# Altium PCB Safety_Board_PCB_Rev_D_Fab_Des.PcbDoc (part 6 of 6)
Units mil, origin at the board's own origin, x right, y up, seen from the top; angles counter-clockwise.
Board outline 11000 x 4400 mil, 6 copper layers (L1-TOP, L2-Plane, L3-Signal, L4-Signal, L5-Plane, L6-BOT); 712 components, 540 nets, 2214 pads, 875 vias.
Unrouted connection lines stored in the file: 3.
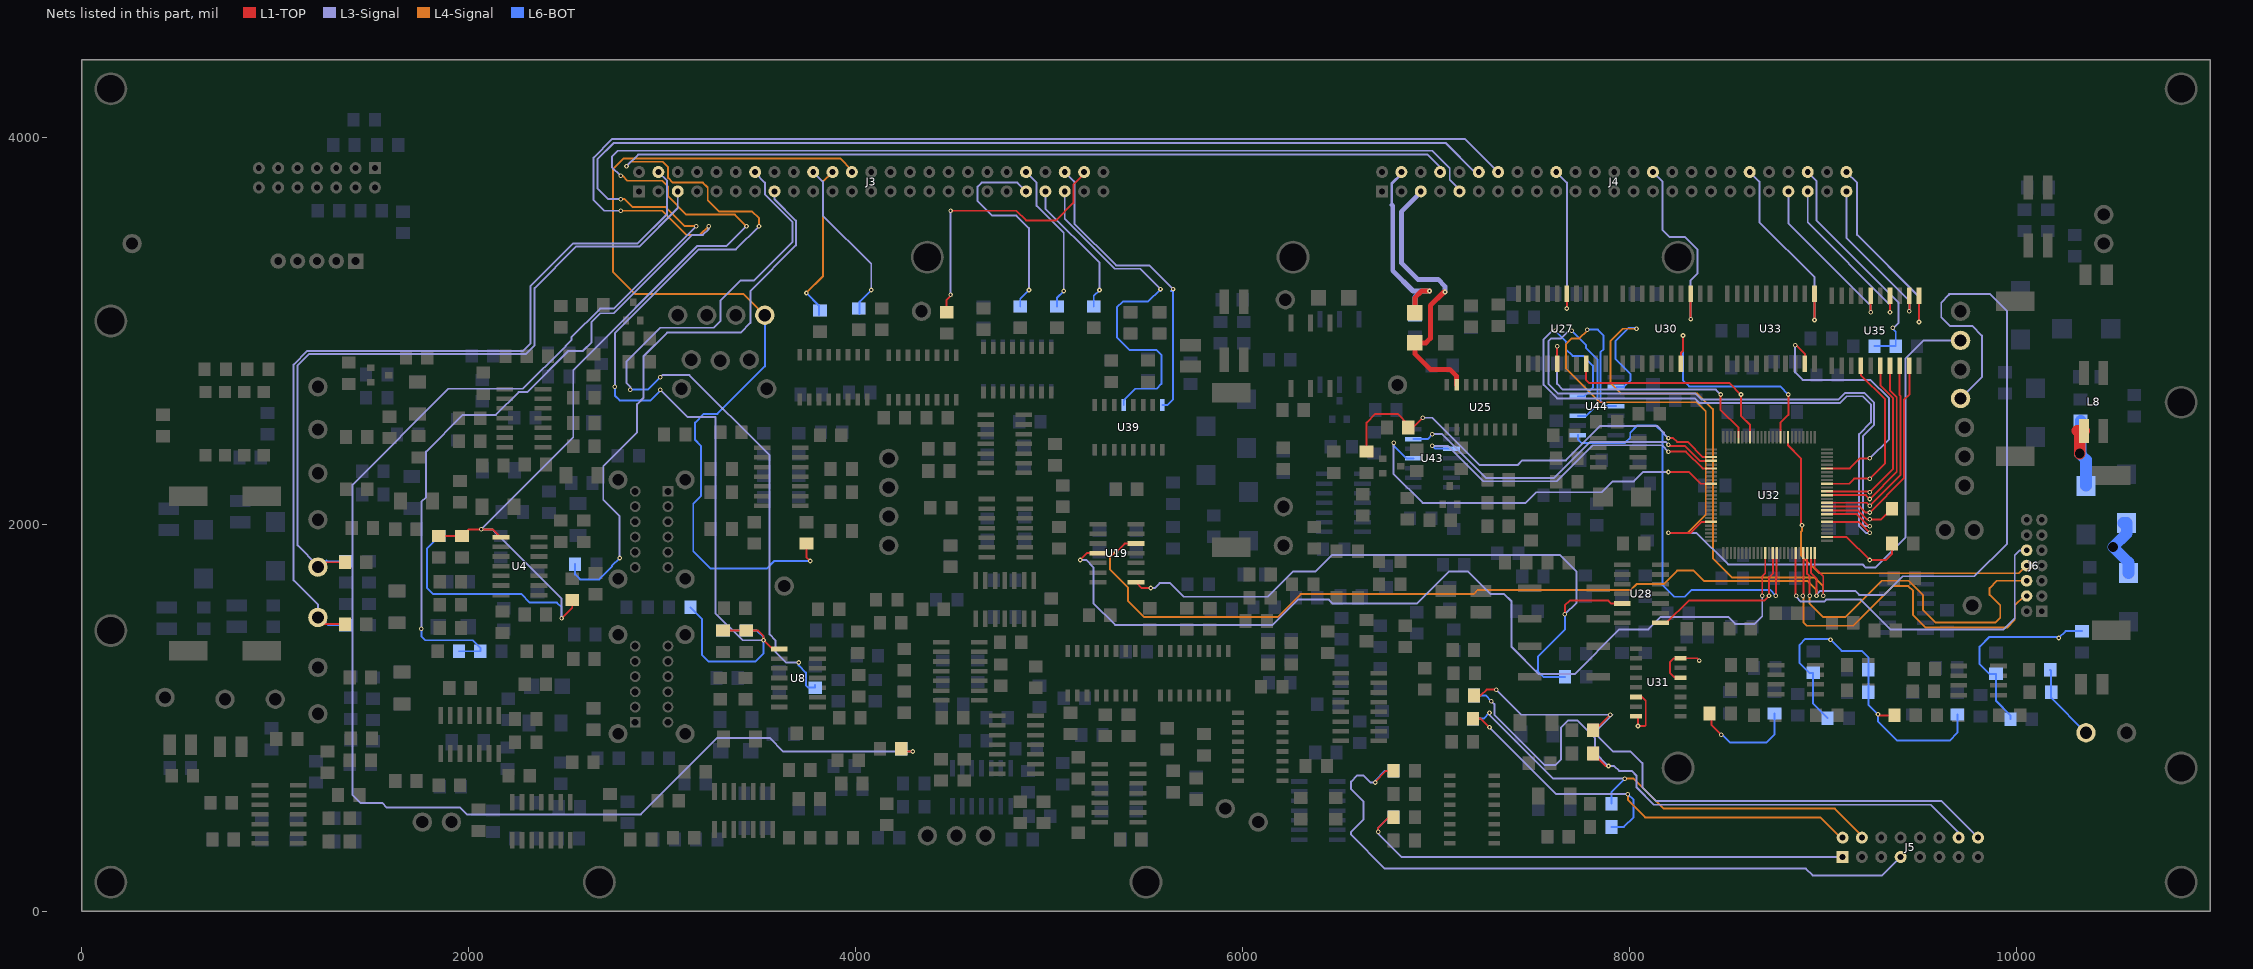
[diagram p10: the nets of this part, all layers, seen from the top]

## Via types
v1: diameter 24, hole 12, L1-TOP to L6-BOT, 720 vias
v2: diameter 50, hole 28, L1-TOP to L6-BOT, 138 vias
v3: diameter 28, hole 50, L1-TOP to L6-BOT, 17 vias

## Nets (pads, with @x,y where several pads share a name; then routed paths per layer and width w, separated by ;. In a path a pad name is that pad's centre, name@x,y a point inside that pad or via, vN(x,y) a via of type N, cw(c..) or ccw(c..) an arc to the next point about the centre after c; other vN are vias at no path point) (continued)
"SOUTH TACH OUT": C9.1 C66.1 J4.9 R26.1 R37.1 R211.1 U4.1 | length 10012.3
  L1-TOP w10: C9.1@1844.65,1938.23 R26.1@1964.65,1938.23 ; R26.1@1969.76,1933.11 R26.1@1964.65,1938.23 ; U4.1@2159.65,1933.11 U4.1@2166.22,1933.11 U4.1@2161.1,1938.23 ; U4.1@2164.65,1933.11 2124.65,1973.11 1999.53,1973.11 R26.1@1964.65,1938.23 ; v1(2479.65,1513.11) 2534.65,1568.11 R37.1@2534.65,1607.99
  L4-Signal w10: v1(2785,3800) 2795,3800 2820,3775 3000,3775 3030,3745 3030,3695 3125,3600 3375,3600 v1(3435,3540)
  L3-Signal w10: v1(2064.65,1973.11) 2121.89,1973.11 2479.65,1615.35 v1(2479.65,1513.11) ; v1@2064.65,1974.65 2540,2450 2540,2795.96 3182.04,3438 3333,3438 v1(3435,3540) ; v1(2785,3800) 2740,3845 2740,3900 2770,3930 6980,3930 7070,3840 7070,3780 7120,3730 J4.9@7120,3720
  L6-BOT w10: C66.1@1968.23,1938.23 R211.1@1844.65,1938.23 1844.65,1934.65 1785,1875 1785,1670 1815,1640 2270,1640 2315,1595 2455,1595 2479.65,1570.35 v1(2479.65,1513.11)
"SOUTH VEL IN": J3.15 R230.2 | length 2953.5
  L3-Signal w10: v1(2780,1825) 2780,2040 2695,2125 2695,2300 2870,2475 2870,2620 2902.98,2652.98 2902.98,2867.98 3025,2990 3405,2990 3455,3040 3455,3205 3691,3441 3691,3569 3580,3680 J3.15@3580,3720
  L6-BOT w10: R230.2@2549.53,1793.11 2549.53,1740.47 2575,1715 2675,1715 2740,1780 2740,1785 v1(2780,1825)
"SOUTH VEL OUT": C67.2 J4.14 R215.2 | length 9152.5
  L4-Signal w10: v1(2785,3620) 3000,3620 3125,3495 3195,3495 v1(3240,3540) 3240,3525
  L3-Signal w10: v1(1755,1460) 1755,2115 1780,2140 1780,2375 1970,2565 2140,2565 2258,2683 2303,2683 2515,2895 2590,2895 2635,2940 2635,3045 2680,3090 2750,3090 3155,3495 3210,3495 3240,3525 v1(3240,3540) ; v1(2785,3620) 2700,3620 2645,3675 2645,3895 2740,3990 7150,3990 J4.14@7320,3820 J4.14@7320,3830
  L6-BOT w10: v1(1755,1460) 1755,1420 1775,1400 2020,1400 2059.53,1360.47 C67.2@2059.53,1343.11 R215.2@1949.76,1343.11
SOUTH_ENCODER_BUF: J5.7 R138.1 R318.2 | length 3695.4
  L1-TOP w10: v1(6685,665) 6685,670 6740,725 R138.1@6779.88,725
  L3-Signal w10: v1(6685,665) 6660,665 6625,700 6590,700 6560,670 6560,630 6625,565 6625,475 6560,410 6560,395 6735,220 8910,220 8945,185 9305,185 J5.7@9400,280
  L6-BOT w10: v1(6685,665) 6685,675 6735,725 R318.2@6779.88,725
SOUTH_ENCODER_IN: J5.14 R166.1 R330.1 | length 3329.8
  L1-TOP w10: R166.1@7810.12,815 7875.12,750 v1(7890,750)
  L3-Signal w10: v1(7285,1085) 7300,1070 7300,1015 7560,755 7615,755 7645,785 7645,950 7680,985 7730.96,985 7820,895.96 7820,820 v1(7890,750) 7920,750 7945,725 8010,725 8035,700 8035,640 8125,550 9555,550 9700,405 J5.14@9700,380
  L6-BOT w10: R330.1@7195.12,1115 7255,1115 v1(7285,1085)
SOUTH_ENCODER_RTN: J5.16 R155.1 R165.1 | length 3330.2
  L1-TOP w10: R155.1@7195.12,1115 7230,1115 7260,1145 v1(7310,1145) ; R165.1@7810.12,960.12 R165.1@7810.12,935 7820,935 v1(7900,1015)
  L3-Signal w10: v1(7310,1145) 7440,1015 v1(7900,1015) 7910,1015 7905,1010 7830,935 7830,910 7915,825 8005,825 8065,765 8065,640 8135,570 9610,570 J5.16@9800,380
SOUTH_OVERCURRENT_LATCH: U27.8 U32.93 | length 1155
  L1-TOP w10: U27.8@7775,2828.9 7775,2745 7791,2729 8516,2729 v1(8575,2670) 8575,2560 8621.57,2513.43 U32.93@8621.57,2449.21
SOUTH_OVERCURRENT_N: TP41.1 U32.20 U44.4 | length 5241
  L1-TOP w10: v1(8200,1955) 8315,1955 8372.2,2012.2 U32.20@8420.79,2012.2
  L4-Signal w10: v1(7780,3005) 7780,3000 7740,2960 7700,2960 7670,2930 7670,2805 7845,2630 8346.92,2630 8393,2583.92 8393,2048 8300,1955 v1(8200,1955)
  L3-Signal w10: v1(8200,1955) 8345,1955 8508,1792 9203,1792 9220,1775 9270,1775 9425,1930 9425,2855 9520,2950 TP41.1@9710,2950
  L6-BOT w10: v1(7780,3005) 7835,3005 7865,2975 7865,2905 7850,2890 7850,2635 7875,2610 U44.4@7928.43,2610
SPARE1_BUF: U32.40 U44.8 | length 2183.4
  L1-TOP w10: v1(8755,1630) 8755,1725 8759.37,1729.37 U32.40@8759.37,1850.79
  L6-BOT w10: U44.8@7731.57,2460 7731.57,2438.43 7750,2420 7975,2420 8002.57,2447.57 8002.57,2472.57 8040,2510 8135,2510 8170,2475 8170,1685 8230,1625 8285,1625 8320,1660 8725,1660 v1(8755,1630)
SPARE1_LATCH: U32.64 U35.6 | length 953.3
  L1-TOP w10: U32.64@9019.21,2169.69 9235.31,2169.69 v1(9240,2165) 9360,2285 9360,2653.08 9295,2718.08 U35.6@9295,2818.9
SPARE2_BUF: U32.58 U44.10 | length 3614.2
  L1-TOP w10: U32.58@9019.21,2051.57 9174.38,2051.57 v1@9235.96,1990
  L4-Signal w10: v1@7695,3000 v1(7700,3000)
  L3-Signal w10: v1(7700,3000) 7685,3000 7645,2960 7595,2960 7580,2945 7580,2725 7630,2675 8340,2675 8370,2645 9080,2645 9113,2678 9212.96,2678 9263,2627.96 9263,2513 9205,2455 9205,2000 9215,1990 v1(9240,1990)
  L6-BOT w10: v1(7700,3000) 7775,2925 7775,2910 7833,2852 7833,2618 7775,2560 U44.10@7731.57,2560
SPARE2_LATCH: U32.63 U35.7 | length 990.5
  L1-TOP w10: U32.63@9019.21,2150 9220,2150 v1(9240,2130) 9380,2270 9380,2657.12 9345,2692.12 U35.7@9345,2818.9
"SPARE IN 1": J3.45 U39.4 | length 1889
  L3-Signal w10: J3.45@5080,3720 5080,3578.08 5338.08,3320 5470,3320 v1(5575,3215)
  L6-BOT w10: U39.4@5385,2615.16 5385,2640 5445,2700 5555,2700 5580,2725 5580,2875 5555,2900 5415,2900 5350,2965 5350,3120 5380,3150 5510,3150 v1(5575,3215) v1@5575,3205
"SPARE IN 2": J3.46 U39.8 | length 1589.7
  L3-Signal w10: J3.46@5080,3820 5130,3770 5130,3552.12 5345.12,3337 5518,3337 v1(5640,3215)
  L6-BOT w10: U39.8@5585,2615.16 5610.16,2615.16 5640,2645 v1(5640,3215) 5630,3205
"SPARE LATCH OUT 1": J4.45 U35.14 | length 887.1
  L1-TOP w10: v1(9345,3095) U35.14@9345,3181.1
  L3-Signal w10: J4.45@8920,3720 8920,3560 9345,3135 v1(9345,3095)
"SPARE LATCH OUT 2": J4.46 R374.2 R376.2 | length 1233
  L3-Signal w10: J4.46@8920,3820 8965,3775 8965,3570 9390,3145 9390,3040 9365,3015 v1(9360,3015)
  L6-BOT w10: R374.2@9265.12,2920 R376.2@9374.88,2920 9374.88,2995.12 9355,3015 v1(9360,3015)
SPARE_RESISTOR1: R179.1 U32.59 | length 377.6
  L1-TOP w10: U32.59@9019.21,2071.26 9178.74,2071.26 9225,2025 9299.88,2025 R179.1@9354.88,2080
  other v1: 9240,2025
SPARE_RESISTOR2: R180.1 U32.52 | length 452.2
  L1-TOP w10: U32.52@9019.21,1933.46 9121.54,1933.46 v1(9240,1815) 9325,1815 9354.88,1844.88 R180.1@9354.88,1900
TCK: J6.6 U32.48 | length 1886.3
  L1-TOP w10: U32.48@8916.85,1850.79 8916.85,1743.15 8930,1730 v1(8930,1630)
  L4-Signal w10: v1(8930,1630) 8930,1590 9000,1520 9115,1520 9302.48,1707.48 9442.52,1707.48 9515,1635 9515,1556.56 9579.56,1492 9890.48,1492 9915,1516.52 9915,1580 9860,1635 9860,1670 9897.48,1707.48 J6.6@10051.26,1707.48
"TCS LOCKOUT": J3.20 R260.1 | length 891.1
  L3-Signal w10: J3.20@3780,3820 3830,3770 3830,3595 4080,3345 v1(4080,3210) v1@4085,3215
  L6-BOT w10: R260.1@4020,3085.12 4020,3150 v1(4080,3210)
"TCS LOCKOUT LATCH": J4.30 U30.13 | length 1047.7
  L1-TOP w10: v1(8315,3060) U30.13@8315,3191.1
  L3-Signal w10: J4.30@8120,3820 8170,3770 8170,3520 8205,3485 8285,3485 8350,3420 8350,3295 8315,3260 v1(8315,3060)
TCS_LOCKOUT_BUF_N: U19.4 U32.37 | length 4852.1
  L1-TOP w10: v1(5160,1815) 5195,1850 U19.4@5251.57,1850 ; v1(8685,1630) 8685,1730 8700.32,1745.31 U32.37@8700.32,1850.79
  L3-Signal w10: v1(5160,1815) 5190,1815 5228,1777 5228,1592 5340,1480 6155,1480 6285,1610 6445,1610 6465,1590 6900,1590 7065,1755 7165,1755 7280,1640 7350,1640 7389,1601 7389,1366 7530,1225 7715,1225 7946,1456 8096,1456 8161,1521 8509,1521 8545,1485 8645,1485 8685,1525 v1(8685,1630)
TCS_LOCKOUT_LATCH: U30.7 U32.85 | length 1194.6
  L1-TOP w10: U30.7@8265,2828.9 8265,2885 8275,2895 v1(8275,2975) ; U32.85@8779.06,2449.21 8779.06,2524.06 8820,2565 v1(8820,2670)
  L6-BOT w10: v1(8275,2975) 8275,2744.04 8307.04,2712 8778,2712 v1(8820,2670)
TDI: J6.10 U32.45 | length 1856.9
  L1-TOP w10: U32.45@8857.8,1850.79 8857.8,1632.2 v1(8860,1630)
  L3-Signal w10: v1(8860,1630) 8860,1625 8885,1600 9005,1600 9015,1610 9195,1610 9350,1455 9930,1455 9990,1515 9990,1840 10014.96,1864.96 J6.10@10051.26,1864.96
TDO: J6.8 U32.83 | length 1862.6
  L1-TOP w10: U32.83@8818.43,2449.21 8818.43,2406.57 8885,2340 8885,2000 v1(8890,1995)
  L4-Signal w10: v1(8890,1995) 8890,1965 8885,1960 8885,1840 8978.78,1746.22 10011.26,1746.22 J6.8@10051.26,1786.22
"TEL AMP": D11.K J4.4 R327.1 | length 1114.6
  L1-TOP w25: D11.K@6890,3093.5 6890,3170 6925,3205 v1(6965,3205)
  L3-Signal w15: 6770,3650 6770,3760 6820,3810 J4.4@6820,3820
  L3-Signal w25: 6770,3650 6775,3645 6775,3310 6880,3205 v1(6965,3205)
  L6-BOT w25: R327.1@6890,3080.12 6890,3175 6920,3205 v1(6965,3205)
"TEL AMP ENABLE & THERM STAT LATCH": J4.43 U35.16 | length 887.1
  L1-TOP w10: v1(9245,3095) U35.16@9245,3181.1
  L3-Signal w10: J4.43@8820,3720 8820,3555 9245,3130 v1(9245,3095)
"TEL AMP RET": D11.A J4.5 U25.15 | length 1443.8
  L1-TOP w25: v1(7045,3200) 7040,3200 6970,3130 6970,2960 6946.5,2936.5 D11.A@6890,2936.5 6890,2880 6970,2800 7070,2800 7105,2765 U25.15@7105,2720.16
  L3-Signal w25: J4.5@6920,3720 6920,3715 6820,3615 6820,3350 6905,3265 7010,3265 7045,3230 v1(7045,3200)
TEL_AMP_ENABLE_&_THERM_STAT: U32.6 U43.10 | length 1748.1
  L1-TOP w10: v1(8200,2375) 8290,2375 8377.2,2287.8 U32.6@8420.79,2287.8
  L3-Signal w10: v1(6980,2405) 7060,2405 7243,2222 7622,2222 7808,2408 8167,2408 v1(8200,2375)
  L6-BOT w10: v1(6980,2405) 6995,2390 U43.10@7078.43,2390
TEL_AMP_ENABLE_&_THERM_STAT_LATCH: U32.66 U35.4 | length 900.3
  L1-TOP w10: U32.66@9019.21,2209.06 9134.06,2209.06 9160,2235 v1(9240,2235) 9320,2315 9320,2645 9195,2770 U35.4@9195,2818.9
TEL_BRAKE_RELEASE_&_AMP_ENABLE_N: R142.2 R144.2 U32.3 | length 2263
  L1-TOP w10: R142.2@6640,2375.12 6640,2525 6685,2570 6800,2570 6855.12,2514.88 R144.2@6855.12,2500 6880,2500 v1(6930,2550) ; v1(8200,2445) 8225,2445 8245,2425 8300,2425 8378.15,2346.85 U32.3@8420.79,2346.85
  L3-Signal w10: v1(6930,2550) 6980,2550 7225,2305 7420,2305 7445,2330 7670,2330 7848,2508 8142,2508 8177.06,2472.94 8177.06,2467.94 v1(8200,2445)
TMS: J6.4 U32.47 | length 1891.4
  L1-TOP w10: v1(8895,1630) 8897.17,1632.17 U32.47@8897.17,1850.79
  L4-Signal w10: v1@8897.17,1632.17 8897.17,1630 8897.17,1492.83 8915,1475 9155,1475 9360,1680 9440,1680 9465,1655 9465,1530 9530,1465 9950,1465 9990,1505 9990,1580 10038.74,1628.74 J6.4@10051.26,1628.74
  L3-Signal w10: v1@8895,1620 v1(8895,1630)
"TOP BRAKE ENABLE OUT": J4.50 U35.11 | length 1066.4
  L1-TOP w10: v1(9495,3045) U35.11@9495,3181.1
  L3-Signal w10: J4.50@9120,3820 9175,3765 9175,3495 9495,3175 v1(9495,3045)
"TOP DOMECNTL HANDPADDLE": J3.48 R82.2 | length 1416
  L1-TOP w10: R82.2@4470,3095.12 4470,3160 4495,3185 v1(4490,3185) ; v1(4490,3620) 4830,3620 4880,3570 5035,3570 5125,3660 5125,3755 5180,3810 J3.48@5180,3820
  L3-Signal w10: v1(4490,3185) v1(4490,3620)
"TOP DOMECNTL SOFTWARE": J3.41 R274.2 | length 1098.4
  L3-Signal w10: J3.41@4880,3720 4835,3765 4650,3765 4630,3745 4630,3670 4705,3595 4830,3595 4895,3530 v1(4895,3210)
  L6-BOT w10: R274.2@4850,3125.12 4850,3165 v1(4895,3210)
"TOP LM OVERRIDE SWITCH": J3.43 R286.2 | length 723.3
  L3-Signal w10: J3.43@4980,3720 4980,3630 5260,3350 v1(5260,3210)
  L6-BOT w10: R286.2@5230,3125.12 5230,3180 v1(5260,3210)
"TOP TCS ENABLE": J4.49 U35.12 | length 835.7
  L1-TOP w10: v1(9445,3100) U35.12@9445,3181.1
  L3-Signal w10: J4.49@9120,3720 9120,3480 9445,3155 v1(9445,3100)
"TOP TEL ENABLE SWITCH": J3.42 R280.2 | length 790.2
  L3-Signal w10: J3.42@4880,3820 4935,3765 4935,3645 5075,3505 v1(5075,3205)
  L6-BOT w10: R280.2@5040,3125.12 5040,3170 v1(5075,3205)
TOP_BRAKE_ENABLE_OUT: U32.60 U35.9 | length 1077.4
  L1-TOP w10: U32.60@9019.21,2090.94 9189.06,2090.94 9220,2060 v1(9240,2060) 9417,2237 9417,2642 9445,2670 U35.9@9445,2818.9
TOP_DOME_CNTL_HANDPADDLE_BUF: U32.50 U44.2 | length 3115.4
  L1-TOP w10: U32.50@8956.22,1850.79 8956.22,1773.78 9000,1730 v1(9000,1630)
  L4-Signal w10: v1(8035,3010) 7965,3010 7900,2945 7900,2730 7955,2675 8350,2675 8430,2595 8430,1825 8531,1724 8956,1724 9000,1680 v1(9000,1630)
  L6-BOT w10: U44.2@7928.43,2710 7970,2710 8005,2745 8005,2775 7927,2853 7927,2947 7995,3015 8030,3015 v1(8035,3010)
TOP_DOME_CNTL_SOFTWARE_BUF: U32.10 U43.4 | length 2098.5
  L1-TOP w10: v1(8200,2270) 8305.96,2270 8366.9,2209.06 U32.10@8420.79,2209.06
  L3-Signal w10: v1(6780,2420) 6780,2259.04 6929.04,2110 7461.71,2110 7516.71,2165 7855,2165 7911,2221 8021,2221 8070,2270 v1(8200,2270)
  L6-BOT w10: v1(6780,2420) 6780,2405 6845,2340 U43.4@6881.57,2340
TOP_LM_OVERRIDE_SWITCH_BUF: U32.56 U44.12 | length 3547.9
  L1-TOP w10: U32.56@9019.21,2012.2 9182.8,2012.2 v1(9240,1955)
  L3-Signal w10: v1(7615,3000) 7600,3000 7555,2955 7555,2720 7625,2650 8335,2650 8358,2627 9087,2627 9121,2661 9204,2661 9246,2619 9246,2526 9185,2465 9185,1990 9220,1955 v1(9240,1955)
  L6-BOT w10: v1(7615,3000) 7670,2945 7670,2905 7705,2870 7760,2870 7810,2820 7810,2705 7765,2660 U44.12@7731.57,2660
TOP_TCS_ENABLE: U32.61 U35.8 | length 1019.5
  L1-TOP w10: U32.61@9019.21,2110.63 9224.37,2110.63 v1(9240,2095) 9400,2255 9400,2661.17 9395,2666.17 U35.8@9395,2818.9
TOP_TEL_ENABLE_SWITCH_BUF: U32.4 U43.6 | length 1760.7
  L1-TOP w10: v1(8200,2410) 8205,2405 8285,2405 8362.83,2327.17 U32.4@8420.79,2327.17
  L3-Signal w10: v1(6980,2465) 7030,2465 7256,2239 7609,2239 7795,2425 8185,2425 v1(8200,2410)
  L6-BOT w10: U43.6@6881.57,2440 6955,2440 v1(6980,2465)
"WATCHDOG IN": J3.22 R253.1 | length 822.7
  L4-Signal w10: v1(3745,3195) 3830,3280 3830,3770 J3.22@3880,3820
  L6-BOT w10: v1(3745,3195) 3810,3130 R253.1@3810,3080.12
"WATCHDOG TIMER LATCH": J4.40 U33.11 | length 1039.9
  L1-TOP w10: v1(8955,3055) U33.11@8955,3191.1
  L3-Signal w10: J4.40@8620,3820 8670,3770 8670,3560 8955,3275 v1(8955,3055)
WATCHDOG_IN_BUF: R349.1 U19.8 U28.5 | length 3567.5
  L1-TOP w10: U19.8@5448.43,1700 5478.43,1670 v1(5525,1670) ; v1(7665,1535) 7665,1580 7690,1605 7890,1605 7905,1590 U28.5@7961.57,1590
  L3-Signal w10: v1(5525,1670) 5545,1670 5570,1695 5625,1695 5695,1625 6128.83,1625 6258.83,1755 6375,1755 6460,1840 7640,1840 7725,1755 7725,1595 v1(7665,1535)
  L6-BOT w10: 7520,1245 7553.74,1211.26 R349.1@7664.88,1211.26 ; 7525,1240 7525,1315 7665,1455 v1(7665,1535)
WATCHDOG_TIMER_ERROR_N: U28.8 U32.39 | length 848.5
  L1-TOP w10: U28.8@8158.43,1490 8190,1490 8305,1605 8695,1605 v1(8720,1630) 8720,1725 8739.68,1744.69 U32.39@8739.68,1850.79
WATCHDOG_TIMER_LATCH: U32.70 U33.9 | length 1394.5
  L1-TOP w10: v1(8855,2925) 8860,2925 8905,2880 U33.9@8905,2828.9 ; U32.70@9019.21,2287.8 9137.8,2287.8 9190,2340 v1(9240,2340)
  L3-Signal w10: v1(8855,2925) 8855,2785 8894,2746 9244,2746 9340,2650 9340,2440 v1(9240,2340)
WDGND: C41.1 C43.1 C153.1 C160.1 C163.2 C164.2 C165.2 L8.3 R366.1 R370.1 R373.1 R375.1 R379.1 R381.1 R384.1 R385.1 R388.2 R390.1 TP49.1 U31.6 U31.8 U31.13 U31.15 | length 5191.1
  L1-TOP w10: U31.8@8032.81,1006.92 8042.96,996.76 v1(8042.96,956.92) 8077.96,956.92 8082.96,961.92 8082.96,1086.92 8062.96,1106.92 U31.6@8032.81,1106.92 ; 8227.96,1306.92 8207.96,1286.92 8207.96,1231.92 8232.96,1206.92 U31.13@8263.12,1206.92 ; U31.15@8263.12,1306.92 8348.08,1306.92 v1(8360,1295) ; C41.1@8422.96,996.92 8422.96,961.92 v1(8472.96,911.92) ; v1(9282.96,1016.92) 9287.96,1011.92 C43.1@9367.85,1011.92
  L1-TOP w60: 10312.85,2481.92 L8.3@10347.96,2481.92 10325,2458.95 v3(10325,2365)
  L6-BOT w10: v1(8472.96,911.92) 8477.96,911.92 8517.96,871.92 8707.96,871.92 8747.96,911.92 R366.1@8747.96,1021.8 ; C153.1@9022.85,996.92 8947.96,1071.8 R370.1@8947.96,1231.8 8928.08,1231.8 8877.96,1281.92 8877.96,1376.92 8907.96,1406.92 9032.96,1406.92 9094.88,1345 9200,1345 9233.08,1311.92 R375.1@9233.08,1136.92 ; R375.1@9233.08,1131.92 9233.08,1066.8 v1(9282.96,1016.92) 9282.96,981.92 9382.96,881.92 9652.96,881.92 9692.96,921.92 R379.1@9692.96,1016.8 ; C160.1@9967.85,991.92 9967.85,1012.04 9892.96,1086.92 R381.1@9892.96,1226.8 9858.08,1226.8 9807.96,1276.92 9807.96,1366.92 9857.96,1416.92 10212.96,1416.92 v1(10217.96,1411.92) 10253.08,1447.04 R390.1@10337.97,1447.03 ; R384.1@10173.08,1246.92 10178.08,1241.92 10178.08,1101.8 TP49.1@10357.97,921.92
  L6-BOT w60: R388.2@10330,2534.88 10330,2370 v3(10325,2365) 10357.96,2332.04 C163.2@10357.96,2197.9 ; C164.2@10549.93,2005.93 C164.2@10567.96,2005.93 10567.96,1951.92 v3(10497.96,1881.92) 10577.96,1801.92 C165.2@10577.96,1747.9
  other v1: 9037.96,1401.92
"WEST CURRENT": J3.24 R61.1 TP21.1 | length 4896.8
  L1-TOP w10: R61.1@3745,1899.88 3745,1830 v1(3765,1810)
  L4-Signal w10: TP21.1@3530,3080 3421,3189 2861.21,3189 2745,3305.21 2745,3835 2800,3890 3920,3890 3980,3830 J3.24@3980,3820
  L6-BOT w10: TP21.1@3530,3080 3530,2815 3285,2570 3215,2570 3170,2525 3170,2435 3200,2405 3200,2145 3160,2105 3160,1860 3250,1770 3540,1770 3580,1810 v1(3765,1810)
"WEST DRIVE+": C56.2 J3.4 R14.1 TP10.1 | length 4336.4
  L1-TOP w10: TP10.1@1219.65,1518.11 1254.65,1483.11 R14.1@1359.53,1483.11
  L3-Signal w10: TP10.1@1220,1518.11 1220,1585 1095,1710 1095,2825 1166,2896 2281,2896 2315,2930 2315,2930.96 2320,2935.96 2320,3231.92 2539.08,3451 2872.92,3451 3025,3603.08 3025,3775 J3.4@2980,3820
  L6-BOT w10: TP10.1@1219.65,1518.11 1234.65,1518.11 1274.76,1477.99 C56.2@1364.65,1477.99
"WEST DRIVE-": C53.2 J3.5 R13.1 TP9.1 | length 3984.3
  L1-TOP w10: TP9.1@1229.65,1778.11 1254.65,1803.11 R13.1@1359.53,1803.11
  L3-Signal w10: TP9.1@1220,1778.11 1220,1785 1115,1890 1115,2820.96 1173.04,2879 2294,2879 2340,2925 2340,3220 2554,3434 2879.96,3434 3080,3634.04 J3.5@3080,3720
  L6-BOT w10: 1264.76,1813.23 1229.65,1778.11 1239.65,1778.11 1269.76,1808.23 C53.2@1364.65,1808.23
"WEST OC LATCH": J4.20 U27.15 | length 803.9
  L1-TOP w10: v1(7675,3115) U27.15@7675,3191.1
  L3-Signal w10: J4.20@7620,3820 7675,3765 v1(7675,3115)
"WEST TACH OUT": C22.1 C82.1 J4.8 R57.2 R240.2 R246.1 U8.1 | length 9703
  L1-TOP w10: R57.2@3313.43,1450.12 3494.88,1450.12 3523.43,1421.57 v1(3523.43,1400) 3568.43,1355 U8.1@3605,1355
  L4-Signal w10: v1(2815,3850) 2838,3873 3002,3873 3030,3845 3030,3790 3055,3765 3210,3765 3235,3740 3235,3675 3293,3617 3463,3617 3500,3580 v1(3500,3540)
  L3-Signal w10: v1(2755,2710) 2755,2986.92 3188.08,3420 3380,3420 v1(3500,3540) ; v1(2815,3850) 2875,3910 6955,3910 7020,3845 J4.8@7020,3820 ; v1(2990,2695) 3130,2555 3275,2555 3275,1540 3415,1400 v1@3525,1400 ; v1@3523.43,1393.43 v1(3523.43,1400)
  L6-BOT w10: v1(2755,2710) 2755,2665 2780,2640 2940,2640 2990,2690 v1(2990,2695) ; R240.2@3145.12,1570 3205,1510.12 3205,1325 3240,1290 3480,1290 3523.43,1333.43 v1(3523.43,1400) ; R246.1@3313.43,1450.12 3488.31,1450.12 3523.43,1415
"WEST VEL IN": J3.14 R256.1 | length 4065.6
  L3-Signal w10: v1(2835,2695) 2835,2710 2815,2730 2815,2840 2990,3015 3265,3015 3300,3050 3300,3155 3405,3260 3475,3260 3674,3459 3674,3561 3530,3705 3530,3765 3480,3815 J3.14@3480,3820 ; v1(2990,2760) 3000,2770 3140,2770 3555,2355 3555,1430 3585,1400 3585,1340 3640,1285 v1(3705,1285)
  L6-BOT w10: v1(2835,2695) 2925,2695 v1(2990,2760) ; v1(3705,1285) 3705,1270 3742.57,1232.43 3742.57,1167.43 3755.12,1154.88 R256.1@3790,1154.88 R256.1@3790,1170
"WEST VEL OUT": C92.2 J4.12 R80.2 | length 12596.1
  L1-TOP w10: R80.2@4235.12,840 4250.12,825 v1(4295,825)
  L4-Signal w10: v1(2785,3680) 2805,3680 2845,3640 3015.96,3640 3115.96,3540 v1(3175,3540)
  L3-Signal w10: v1(2785,3680) 2720,3680 2665,3735 2665,3885 2750,3970 7050,3970 7200,3820 J4.12@7220,3820 ; v1(3175,3540) 2748.96,3113.96 2678.96,3113.96 2530,2965 2530,2950.96 2500,2920.96 2500,2920 2280,2700 1895,2700 1400,2205 1400,600 1440,560 1552,560 1577,535 1955,535 1990,500 2890,500 3285,895 3555,895 3625,825 v1(4295,825)
  L6-BOT w10: C92.2@4235.12,840 4250.12,825 v1(4295,825)
WEST_ENCODER_BUF: J5.1 R140.1 R320.2 | length 2705
  L1-TOP w10: v1(6700,410) 6700,430 6755,485 R140.1@6779.88,485
  L3-Signal w10: v1(6700,410) 6700,400 6820,280 J5.1@9100,280
  L6-BOT w10: v1(6700,410) 6700,430 6755,485 R320.2@6779.88,485
WEST_ENCODER_IN: J5.2 R148.1 R353.1 | length 2450.2
  L1-TOP w10: R148.1@7190.12,995 7230,995 v1(7275,950)
  L4-Signal w10: v1(7990,605) 7990,575 8080,485 8985,485 9090,380 J5.2@9100,380
  L3-Signal w10: v1(7275,950) 7620,605 v1(7990,605)
  L6-BOT w10: R353.1@7905.12,435 7970,435 8020,485 8020,575 v1(7990,605)
WEST_ENCODER_RTN: J5.4 R331.1 R352.1 | length 2460.1
  L4-Signal w10: v1(7975,685) 8020,685 8175,530 9060,530 9200,390 J5.4@9200,380
  L3-Signal w10: v1(7275,1025) 7275,1015 7605,685 v1(7975,685)
  L6-BOT w10: R331.1@7190.12,995 7245,995 v1(7275,1025) ; R352.1@7905.12,555 7905.12,615.12 v1(7975,685)
WEST_OVERCURRENT_LATCH: U27.5 U32.96 | length 1413
  L1-TOP w10: U27.5@7625,2828.9 v1(7625,2920) ; v1(8470,2670) 8470,2590 8562.52,2497.48 U32.96@8562.52,2449.21
  L3-Signal w10: v1(7625,2920) 7625,2725 7655,2695 8445,2695 v1(8470,2670)
WEST_OVERCURRENT_N: TP43.1 U19.12 U32.49 | length 7833.4
  L1-TOP w10: v1(5345,1855) 5390,1900 U19.12@5448.43,1900 ; U32.49@8936.54,1850.79 8936.54,1748.46 8965,1720 v1(8965,1630)
  L4-Signal w10: v1(5345,1855) 5340,1855 5315,1830 5315,1765 5408,1672 5408,1602 5490,1520 6180,1520 6299,1639 7194,1639 7215,1660 8005,1660 8035,1690 8175,1690 8245,1760 8330,1760 8383,1707 8918,1707 8965,1660 v1(8965,1630)
  L3-Signal w10: v1(8965,1630) 8965,1635 8985,1655 9165.75,1655 9185.75,1635 9315,1635 9411,1731 9781,1731 9950,1900 9950,3100 9860,3190 9650,3190 9650,3185 9610,3145 9610,3070 9655,3025 9770,3025 9820,2975 9820,2760 TP43.1@9710,2650
pads on no net: D1.3 D8.3 J3.47 J4.48 J6.12 J6.14 L2.2 L2.7 R114.1 R179.2 R180.2 R192.1 R201.1 R241.1 R292.1 SW1. SW1.3 SW1.4 SW1.5 SW1.6 SW1.9 SW1.12 SW2. SW2.3 SW2.4 SW2.5 SW2.6 SW2.9 SW2.12 U5.2 U10.3 U10.4 U10.5 U10.6 U11.13 U16.14 U20.13 U23.3 U23.5 U27.18 U32.2 U32.7 U32.19 U32.24 U32.34 U32.43 U32.46 U32.73 U32.80 U41.3 U41.5 U45.8 U45.10 U45.12

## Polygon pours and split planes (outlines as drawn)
+5V_DIG on L1-TOP (hatched 90Degree grid 5 track 10, remove dead copper): 9830,2425 10205,2425 10205,2200 9825,2200 9825,2425
-15V on L1-TOP (hatched 90Degree grid 0 track 7, remove dead copper): 715,1495 345,1495 345,950 665,950 665,1130 720,1185 720,1495
+15V on L1-TOP (hatched 90Degree grid 0 track 7, remove dead copper): 750,1495 1140,1495 1140,940 810,940 810,1140 750,1200
+5V_WD on L1-TOP (hatched 90Degree grid 0 track 7, remove dead copper): 10257.96,1551.92 10652.96,1551.92 10652.96,1271.92 10262.96,1271.92 10262.96,1551.92
-15V_RAW on L1-TOP (hatched 90Degree grid 0 track 7, remove dead copper): 665,2915 665,2655 390,2655 390,2915
15V_RTN on L1-TOP (hatched 90Degree grid 0 track 7, remove dead copper): 715,2915 715,2665 890,2665 890,2915
CHASSIS on L1-TOP (hatched 90Degree grid 5 track 10, remove dead copper): 3691.62,3887 3816,3503 4057,3503 4057,3792 3957,3792 3957,3887
PCGND on L1-TOP (hatched 90Degree grid 0 track 10, remove dead copper): 3715,3870 3828.36,3520 4040,3520 4040,3775 3940,3775 3940,3870
AGND on L1-TOP (hatched 90Degree grid 0 track 10, remove dead copper): 595,2305 905,2305 905,2180 565,2180 565,2305
CHASSIS on L1-TOP (hatched 90Degree grid 5 track 10, remove dead copper): 33 vertices, not listed, extent 40,58.26 10940,4353.26
-15V on L4-Signal (hatched 90Degree grid 5 track 10, remove dead copper): 45 vertices, not listed, extent 310,300 6080,3245
CHASSIS on L3-Signal (hatched 90Degree grid 5 track 10, remove dead copper): 21 vertices, not listed, extent 60,70 10930,4325
CHASSIS on L3-Signal (hatched 90Degree grid 5 track 10, remove dead copper): 10930,4325 70,4325 70,2950 300,2950 310,2960 480,2960 755,3235 825,3305 825,3905 1125,4205 10930,4205
CHASSIS on L6-BOT (hatched 90Degree grid 5 track 10, remove dead copper): 38 vertices, not listed, extent 43,53.35 10945,4348.35
no net on Top Overlay (hatched 90Degree grid 5 track 10, remove dead copper): 5805,4330 5805,4050 6215,4050 6215,4335 5805,4335
no net on Top Solder (hatched 90Degree grid 5 track 10, remove dead copper): 29 vertices, not listed, extent 65,65 10935,4330
no net on Bottom Solder (hatched 90Degree grid 5 track 10, remove dead copper): 29 vertices, not listed, extent 65,65 10935,4330
+5V_WD on L5-Plane (split plane): 53 vertices, not listed, extent 7950.01,855.02 10684.98,2604.98
EGND on L5-Plane (split plane): 60 vertices, not listed, extent 7170.01,235.02 9894.99,1384.98
+5V_SE_RAW on L5-Plane (split plane): 5755.01,2995.02 5755.01,3122.92 5823.55,3191.45 5823.53,3191.44 ccw(c5820,3195) 5825.01,3195 5825.01,3235 ccw(c5820,3235) 5823.53,3238.56 5823.55,3238.55 5575.01,3487.08 5575.01,3499.98 6139.99,3499.98 6139.99,2995.02
24VGND on L5-Plane (split plane): 18 vertices, not listed, extent 5235.02,2900.02 6744.99,3874.98
+5V_WD_RAW on L5-Plane (split plane): 34 vertices, not listed, extent 1175.01,2595.02 10684.99,4184.98
PCGND on L5-Plane (split plane): 57 vertices, not listed, extent 3660.02,2810.02 5339.98,3874.98
+5V_WD on L5-Plane (split plane): 20.01,20.01 20.01,4379.99 10979.99,4379.99 10979.99,20.01
+5V_SE on L5-Plane (split plane): 93 vertices, not listed, extent 4245.02,1740.02 6419.99,3844.98
+5V_DIG on L5-Plane (split plane): 279 vertices, not listed, extent 3660.02,160.01 10564.99,4054.98
-15V_RAW on L5-Plane (split plane): 315.01,2520.02 1034.99,2520.02 1034.99,2944.98 322.08,2944.98 315.01,2937.92
+15V on L5-Plane (split plane): 167 vertices, not listed, extent 315.01,305.02 9114.99,4054.98
CHASSIS on L5-Plane (split plane): 71 vertices, not listed, extent 65.01,65.01 10934.99,4334.99
+5V_WD_RTN on L2-Plane (split plane): 27 vertices, not listed, extent 9929.35,2595.02 10679.99,4092.74
WDGND on L2-Plane (split plane): 57 vertices, not listed, extent 7947.98,856.93 10679.98,2604.98
EGND on L2-Plane (split plane): 56 vertices, not listed, extent 7170.01,235.02 9894.99,1384.98
+5V_SE_RTN on L2-Plane (split plane): 5755.01,2995.02 5755.01,3122.92 5823.55,3191.45 5823.53,3191.44 ccw(c5820,3195) 5825.01,3195 5825.01,3235 ccw(c5820,3235) 5823.53,3238.56 5823.55,3238.55 5575.01,3487.08 5575.01,3499.98 6139.99,3499.98 6139.99,2995.02
24VGND on L2-Plane (split plane): 18 vertices, not listed, extent 5235.02,2900.02 6744.99,3874.98
+5V_DIG_RTN on L2-Plane (split plane): 22 vertices, not listed, extent 1175.01,3245.02 10249.99,4184.98
PCGND on L2-Plane (split plane): 59 vertices, not listed, extent 3660.02,2810.02 5339.98,3874.98
DGND on L2-Plane (split plane): 20.01,20.01 20.01,4379.99 10979.99,4379.99 10979.99,20.01
SEGND on L2-Plane (split plane): 95 vertices, not listed, extent 4245.02,1740.02 6419.99,3844.98
+15V_RAW on L2-Plane (split plane): 315.01,2520.02 1034.99,2520.02 1034.99,2944.98 317.08,2944.98 315.01,2942.92
DGND on L2-Plane (split plane): 278 vertices, not listed, extent 3660.02,160.01 10564.99,4054.98
AGND on L2-Plane (split plane): 169 vertices, not listed, extent 315.01,305.02 9114.99,4054.98
CHASSIS on L2-Plane (split plane): 71 vertices, not listed, extent 65.01,65.01 10934.99,4334.99

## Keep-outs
Keep-Out Layer:
  lines w10: 50,50 10950,50 10950,4350 50,4350 50,50

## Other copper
L5-Plane (plane layer: these items are gaps in the copper):
  lines w10: 60,1810 310,1810 ; 2575,4060 2575,3575 2250,3240 2250,2950 1040,2950 ; 3655,2805 4560,2805 4605,2850 5140,2850 5175,2815 5175,2585 5230,2530 5655,2530 5680,2505 5715,2505 5715,1755 5735,1735 5935,1735 5980,1780 5980,1810 6245,1810 6275,1840 6275,2115 6240,2150 6240,2180 6180,2180 6145,2215 6145,2745 6215,2745 6215,2645 6425,2645 6425,2895 ; 4240,2805 4240,2960 4290,3010 4390,3010 4430,3050 4430,3165 4345,3245 4270,3310 ; 4350,3240 4270,3310 ; 5345,3880 5345,3785 5330,3770 5230,3770 ; 5570,3505 5570,3485 5820,3235 5820,3195 5750,3125 5750,2990 ; 5750,2995 5750,2990 ; 7480,3535 7570,3625 ; 8110,851.92 8110,645 8165,590 9730,590 9900,420 9900,285 ; 10217.96,2590 10480,2590 10500,2610 10682.96,2610 10690,2617.04 10690,4190 10355,4190 9825,4190 1305,4190 1170,4055 1170,3780 1740,3780 1800,3840 1800,4005 1825,4060 2595,4060 9120,4060 ; 10687.97,2610 10690,850 8227.97,851.92 7948.08,851.92 7945,855 7945,1100 ; 310,2515 310,2940 320,2950 1040,2950 ; 310,2515 1040,2515 1040,2950 ; 310,2515 310,630 310,300 630,300 5830,300 6000,300 ; 4270,3310 4270,3480 4350,3480 4350,3835 4365,3850 5230,3850 5230,3770 ; 5230,3770 5230,3545 5270,3505 5685,3505 6145,3505 6145,3230 6145,2990 ; 5750,2990 5770,2990 6145,2990 ; 6000,300 6175,300 6190,300 6425,300 6570,155 9405,155 9845,155 9850,155 9900,205 9900,285 ; 6000,300 6000,630 6090,630 6090,1095 6045,1125 6045,1175 6020,1200 6020,1220 5760,1220 5735,1245 5060,1245 5060,1375 5105,1425 5105,1965 5135,1995 5135,2455 5015,2580 4600,2580 4525,2505 4105,2505 4035,2570 3895,2570 3880,2585 3685,2585 3655,2625 3655,3160 3735,3245 3735,3855 3750,3875 3755,3875 3915,3875 3925,3865 3925,3795 3950,3770 4005,3770 4030,3745 4030,3685 4285,3685 4315,3715 4315,3880 5315,3880 5330,3880 6750,3880 6750,2925 6720,2895 ; 6145,2990 6145,2965 6215,2895 6425,2895 ; 6425,2895 6720,2895 ; 6720,2895 6720,2655 6940,2655 6985,2610 7160,2610 7230,2540 7230,2430 7245,2415 7245,2370 7260,2355 7375,2355 7455,2380 7455,2490 7320,2645 7255,2645 7235,2665 7235,2755 7255,2775 7255,2820 7280,2845 7310,2845 7325,2860 7325,2900 7280,2945 7280,3335 7570,3625 ; 7570,3625 7570,3745 7545,3770 7495,3770 7470,3795 7470,3910 9050,3910 9050,3810 9030,3790 9000,3790 8985,3765 8975,3745 8975,3695 9000,3650 9055,3650 9090,3685 9090,3840 9120,3870 9120,4060 ; 7945,1100 7945,1180 8105,1180 8105,980 8125,960 8315,960 8340,985 8340,1185 8205,1185 8150,1255 8150,1375 8155,1380 8525,1380 8540,1395 8750,1395 8770,1415 8770,1441.92 10147.97,1441.92 10217.97,1511.92 10217.97,2296.92 10217.96,2857.96 10260,2900 10515,2900 10570,2955 10570,3660 10570,3670 10535,3670 10255,3670 10255,3570 9910,3570 9355,3570 9355,3915 9355,4060 9120,4060 ; 7945,1100 7785,1100 7750,1135 7445,1135 7410,1170 7410,1230 7340,1305 7340,1390 7165,1390 7165,1360 7165,745 7185,700 7185,340 7225,300 8050,300 8080,330 9415,330 9450,295 9450,230 9630,230 9640,240 9640,305 9675,340 9845,340 9900,285 ; 60,60 10940,60 10940,4340 60,4340 60,60
L2-Plane (plane layer: these items are gaps in the copper):
  lines w10: 245,4340 10940,4340 10940,60 60,60 60,4340 275,4340 ; 5230,3770 5330,3770 5345,3785 5345,3880 ; 5570,3505 5570,3485 5820,3235 5820,3195 5750,3125 5750,2990 6145,2990 ; 6170,2745 6145,2745 ; 6425,2895 6425,2645 6220,2645 6215,2640 6215,2735 6205,2745 6145,2745 ; 7942.97,1100 7785,1100 7750,1135 7445,1135 7410,1170 7410,1230 7340,1305 7340,1390 7260,1390 7165,1390 7165,1350 7165,745 7185,700 7185,335 7220,300 8050,300 8080,330 9415,330 9450,295 9450,230 9630,230 9640,240 9640,305 9675,340 9845,340 9900,285 ; 8110,851.92 8110,645 8165,590 8305,590 9730,590 9900,420 9900,285 ; 9917.24,4097.76 10677.24,4097.76 10685,4090 10685,2610 ; 10217.97,2590 10245,2590 10480,2590 10500,2610 10685,2610 ; 10250,3930 10255,3930 ; 10685,2500 10940,2500 ; 310,2515 310,2945 315,2950 1040,2950 ; 310,2515 1040,2515 1040,2950 ; 310,2515 310,630 310,300 630,300 5830,300 6000,300 ; 1040,2950 2250,2950 2250,3240 ; 2250,3240 2575,3575 2575,3910 2575,4060 2715,4060 3870,4060 5030,4060 7350,4060 8230,4060 9120,4060 ; 2250,3240 1335,3240 1270,3305 1270,3550 1170,3650 1170,4055 1305,4190 9825,4190 10035,3980 10035,3930 10255,3930 ; 3655,2805 3655,3160 3735,3245 3735,3855 3750,3875 3915,3875 3925,3865 3925,3845 3925,3795 3950,3770 4005,3770 4030,3745 4030,3685 4285,3685 4315,3705 4315,3880 5305,3880 5330,3880 6700,3880 6750,3880 6750,3865 6750,2925 6720,2895 ; 3655,2805 4240,2805 ; 3655,2805 3655,2625 3685,2585 3880,2585 3895,2570 4035,2570 4105,2505 4525,2505 4555,2535 4600,2580 5015,2580 5135,2455 5135,1995 5105,1965 5105,1425 5060,1375 5060,1325 5060,1245 5245,1245 5425,1245 5735,1245 5760,1220 6020,1220 6020,1200 6045,1175 6045,1125 6090,1095 6090,725 6090,630 6000,630 6000,300 ; 4240,2805 4560,2805 4605,2850 5140,2850 5175,2815 5175,2730 5175,2585 5225,2530 5655,2530 5715,2505 5715,2345 5715,2315 5715,1770 5735,1735 5930,1735 5980,1810 6243.95,1808.95 6275,1870 6275,2115 6240,2180 6180,2180 6145,2215 6145,2225 6145,2745 ; 4240,2805 4240,2960 4245,2965 4290,3010 4390,3010 4430,3050 4430,3165 4270,3310 4270,3480 4350,3480 4350,3835 4365,3850 5230,3850 5230,3735 5230,3545 5270,3505 6145,3505 6145,3150 6145,2990 ; 6000,300 6190,300 6425,300 6570,155 9405,155 9850,155 9900,205 9900,285 ; 6145,2990 6145,2965 6215,2895 6295,2895 6720,2895 ; 6720,2895 6720,2860 6720,2655 6920,2655 6990,2610 7155,2610 7225,2545 7225,2425 7245,2420 7260,2355 7370,2355 7455,2380 7455,2485 7320,2640 7250,2650 7235,2665 7235,2755 7255,2785 7255,2820 7275,2845 7305,2850 7325,2865 7325,2915 7275,2950 7280,3205 7280,3335 7480,3535 7570,3625 7570,3745 7545,3770 7495,3770 7470,3795 7470,3895 7470,3910 9050,3910 9050,3810 9030,3790 9000,3790 8975,3745 8975,3695 9000,3650 9055,3650 9090,3685 9090,3840 9120,3870 9120,4060 ; 9120,4060 9360,4060 9360,3910 9360,3570 9910,3570 10255,3570 10255,3670 ; 10255,3670 10310,3670 10570,3670 10570,3655 10570,2955 10515,2900 10260,2900 10217.97,2857.97 10217.97,2562.97 10217.97,2291.92 10217.97,1506.92 10152.97,1441.92 9695,1440 9695,1400 9310,1400 9290,1370 9120,1370 9065,1445 8770,1445 8750,1395 8540,1395 8525,1380 8245,1380 8170,1380 8150,1375 8147.97,1256.92 8202.97,1186.92 8317.97,1186.92 8337.97,1186.92 8337.97,981.92 8317.97,961.92 8122.97,961.92 8102.97,981.92 8102.97,1146.92 8102.97,1181.92 7942.97,1181.92 7942.97,1131.92 7942.97,881.92 7942.97,851.92 8167.97,851.92 8232.97,851.92 10677.97,851.92 10682.97,856.92 10685,2610 ; 10255,3670 10255,3930

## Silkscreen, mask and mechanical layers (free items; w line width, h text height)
Top Overlay:
  lines w10: 3000,2775 3615,2775 ; 4100,1695 4100,2415 ; 4100,2420 4095,2415 4125,2420 4295,2420 4315,2425 4315,2420 4315,1690 ; 4290,600 4290,320 4755,320 4754.86,604.98 4290,605 ; 9810,2280 9810,2140 9810,2110 ; 9810,3220 9810,3245 9789.88,3245 9670.02,3245 9545,3245 9545,2205 9545,2110 ; 1640.02,599.98 1655,599.98 1710,600 1711.18,598.82 2000,600 2000,596.46 2000,315 1680,315 1680,320.07 1680,490 1640,530 1640,600 ; 1640,600 1640.02,599.98 ; 9545,2110 9640,2110 9785,2110 9810,2110 ; 9545,2110 9545,1810 9885,1810 9885,2110 9810,2110 ; 1140,941.18 1141.18,940 1305,940 1305,2940 1145,2940 1140,2935 1140,941.18 ; 3000,2620 3615,2620 3615,3215 3615,3250 3580,3250 3000,3250 3000,2620
  text "NASA IRTF, University of Hawaii" at 885,4155 h60
  text "TCS3 Safety Board Rev D" at 2745,4145 h60
  text "March 2009" at 4235,4140 h60
  text "Serial #" at 5335,4135 h60
  text "DGND" at 10415,3685 h60
  text "+5VDIG" at 10545,3500 h60 r270
  text "CHASSIS" at 215,3295 h60
  text "PCGND" at 4185,3190 h60
  text "OC" at 9615,3175 h60
  text "CURRENTS" at 3075,3165 h60
  text "N" at 9575,3075 h60
  text "S" at 3055,2945 h60
  text "N" at 3195,2945 h60
  text "E" at 3380,2940 h60
  text "W" at 3510,2940 h60
  text "S" at 9580,2925 h60
  text "D2" at 3255,2920 h60
  text "D3" at 3015,2900 h60 r270
  text "24VGND" at 6150,2900 h60 r90
  text "D1" at 3535,2895 h60 r270
  text "TAC" at 1140,2865 h60
  text "AGND" at 6645,2800 h60
  text "N-" at 1170,2785 h60
  text "E" at 9585,2780 h60
  text "VEL" at 3240,2705 h60
  text "HA" at 3175,2630 h60
  text "DEC" at 3305,2630 h60
  text "W" at 9585,2615 h60
  text "N+" at 1170,2570 h60
  text "D1" at 9565,2475 h60
  text "S-" at 1175,2350 h60
  text "D2" at 9555,2315 h60
  text "N" at 4250,2310 h60
  text "SUMMIT" at 2839.65,2303.11 h60
  text "S" at 4250,2170 h60
  text "D3" at 9555,2170 h60
  text "+5VSE" at 6120,2165 h60
  text "S+" at 1165,2110 h60
  text "OS" at 9655,2040 h60
  text "E" at 4250,2015 h60
  text "SEGND" at 6240,1935 h60 r45
  text "W-" at 1165,1870 h60
  text "W" at 4250,1860 h60
  text "HA" at 9575,1835 h60
  text "DEC" at 9705,1835 h60
  text "AGND" at 3515,1750 h60
  text "BUF" at 4130,1750 h60
  text "JTAG" at 9620,1685 h60
  text "CUR" at 4130,1675 h60
  text "W+" at 1160,1610 h60
  text "LAB" at 2765,1590 h60
  text "SUMMIT" at 2784.65,1498.11 h60
  text "DGND" at 9655,1450 h60
  text "E-" at 1175,1350 h60
  text "+5VWD" at 10595,1271.92 h60 r270
  text "-15V" at 350,1190 h60
  text "+15V" at 900,1185 h60
  text "AGND" at 625,1170 h60
  text "E+" at 1170,1105 h60
  text "WDGND" at 10265,1005 h60
  text "-15V" at 330,945 h60
  text "+15V" at 630,940 h60
  text "LAB" at 2885,790 h60
  text "BUF CUR" at 4290,535 h60
  text "BUFVEL" at 1665,530 h60
  text "D1" at 4330,465 h60
  text "D2" at 4475,465 h60
  text "D3" at 4625,465 h60
  text "AGND" at 5775,390 h60
  text "HA" at 1695,325 h60
  text "DEC" at 1815,325 h60
  text "DGND" at 5915,320 h60
Mechanical 1:
  the board outline again, w20
Mechanical 16:
  lines w5: -2630,-1360 -2430,-1360 ; -2630,1015 -2430,1015 ; -2630,3390 -2430,3390 ; -130,-3735 -130,-3535 ; -130,5565 -130,5765 ; 2370,-3735 2370,-3535 ; 2370,5565 2370,5765 ; 4870,-3735 4870,-3535 ; 4870,5565 4870,5765 ; 6270,-3535 7670,-3535 ; 7370,-3735 7370,-3535 ; 7370,5565 7370,5765 ; 7670,-3235 11560,-3235 ; 7670,-2935 12170,-2935 ; 7670,-2635 12170,-2635 ; 7675,-2630 8175,-2385 8445,-2330 8645,-2325 ; 8640,-2325 8860,-2360 ; 8855,-2360 9490,-2630 ; 9110,-2935 9110,-2635 ; 9340,-2935 9340,-2635 ; 9490,-2635 9490,-2265 ; 9600,-3235 9600,-2935 ; 9870,-3735 9870,-3535 ; 9870,5565 9870,5765 ; 10930,-3235 10930,-2940 ; 11560,-3535 11560,-2935 ; 12170,-1360 12370,-1360 ; 12170,1015 12370,1015 ; 12170,3390 12370,3390 ; 7670,-3535 7670,-2265 9165,-2265 12165,-2265 12170,-3535 ; 7670,-3535 12170,-3535 ; 12170,-3535 -2430,-3535 -2430,5565 12170,5565 12170,-3535 ; -2630,-3735 12370,-3735 12370,5765 -2630,5765 -2630,-3735
  lines w10: -10,0 10,0 ; 0,-10 0,10
  lines w11: 2960,-1623.25 5895,-1623.25 ; 2960,-1427.75 5895,-1427.75 ; 2900,-2852 ccw(c2963,-2852) 2963,-2915 5892,-2915 ccw(c5892,-2852) 5955,-2852 5955,-1263 ccw(c5892,-1263) 5892,-1200 2963,-1200 ccw(c2963,-1263) 2900,-1263 2900,-2852
  text "1" at -1398.66,5635 h70
  text "2" at 1097,5635 h70
  text "3" at 3586.34,5635 h70
  text "4" at 6093.01,5635 h70
  text "5" at 8592,5635 h70
  text "6" at 11097,5635 h70
  text "A" at -2555,4492 h70
  text "A" at 12245,4492 h70
  text "B" at -2555,2112 h70
  text "B" at 12245,2112 h70
  text "0,0 (mil)" at 10,0 h60
  text "C" at -2555,-263 h70
  text "C" at 12245,-263 h70
  text "Layer Stack Up Detail for: Safety_Board_PCB_Rev_D.PcbDoc" at 2960,-1349.18 h51
  text "Layer" at 2960,-1500.75 h45
  text "DIGITAL Areas" at 5010,-1585 h63
  text "Name" at 2960,-1590.75 h45
  text "ANALOG" at 3980,-1595 h63
  text "L1-TOP" at 2960,-1719.27 h63
  text "Component/Routing" at 3665,-1735 h63
  text "Component/Routing" at 4855,-1745 h63
  text "Various GND" at 5000,-1880 h63
  text "AGND" at 4015,-1890 h63
  text "L2-Plane" at 2960,-1900.31 h63
  text "Routing" at 5120,-2050 h63
  text "Routing" at 3925,-2080 h63
  text "L3-Signal" at 2960,-2081.35 h63
  text "Routing" at 5110,-2235 h63
  text "-15V Plane (pour)" at 3655,-2250 h63
  text "L4-Signal" at 2960,-2262.4 h63
  text "University of Hawaii" at 9525,-2380 h90
  text "+5V" at 5205,-2435 h63
  text "L5-Plane" at 2960,-2443.44 h63
  text "+15V" at 3910,-2445 h63
  text "Institute for Astronomy" at 9530,-2570 h130
  text "Component/Routing" at 3595,-2615 h63
  text "Component/Routing" at 4870,-2620 h63
  text "L6-BOT" at 2960,-2624.48 h63
  text "D" at -2555,-2633 h70
  text "D" at 12245,-2633 h70
  text "TITLE" at 9375,-2700 h45
  text "REV" at 9170,-2705 h45
  text "DWG #" at 7700,-2715 h45
  text "TCS3 Safety Board" at 9385,-2855 h90
  text "D" at 9185,-2865 h90
  text "TC3-2072" at 7690,-2875 h90
  text "LAST EDIT" at 9635,-3010 h45
  text "ENGINEER" at 7710,-3020 h45
  text "SHEET" at 11760,-3045 h45
  text "SIZE" at 11010,-3110 h45
  text "B" at 11265,-3150 h150
  text "E. Warmbier" at 7710,-3165 h70
  text ".PRINT_DATE" at 9625,-3170 h70
  text "1 of 1" at 11700,-3310 h90
  text "FILE NAME:" at 7720,-3335 h45
  text ".PCB_FILE_NAME_NO_PATH" at 7770,-3455 h70
  text "1" at -1398.66,-3665 h70
  text "2" at 1097,-3665 h70
  text "3" at 3586.34,-3665 h70
  text "4" at 6093.01,-3665 h70
  text "5" at 8592,-3665 h70
  text "6" at 11097,-3665 h70

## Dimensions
0,4400 to 0,0 on L6-BOT
0,0 to 11000,0 on L6-BOT
0,0 to 0,4400 on Mechanical 16
0,0 to 11000,0 on Mechanical 16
